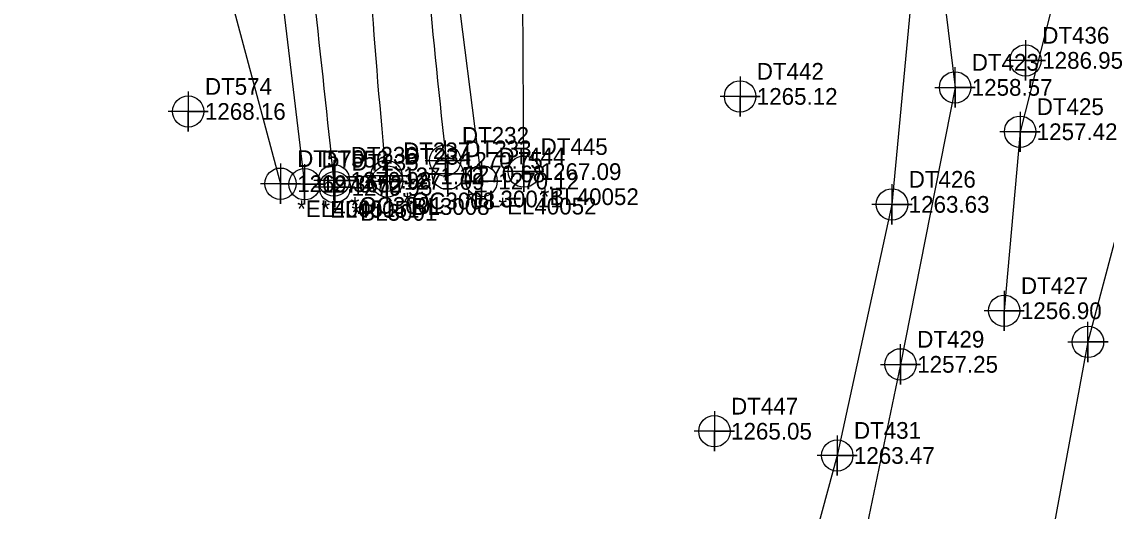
# Model space of a CAD drawing. Extents: x 1391270 to 1392151, y 960049 to 960667.
# Drawn here: x 1391450.5 to 1391612.7, y 960262.4 to 960335.6 of the extents above; entities that cross this region are included whole.
import ezdxf

# ---------------------------------------------------------------- set-up
doc = ezdxf.new("R2010")
doc.units = 0
for name, color, linetype in [('Cogo Default Point CELL', 7, 'Continuous'), ('COGO Default Point Elevation', 7, 'Continuous'), ('COGO Default Point Number', 7, 'Continuous'), ('Exist DTM Breakline', 7, 'Continuous'), ('Exist DTM Breakline Cogo Comment', 7, 'Continuous'), ('Exist DTM Breakline Cogo Elevation', 7, 'Continuous'), ('Exist DTM Breakline Cogo Number', 7, 'Continuous'), ('Exist DTM Breakline Cogo Point CELL', 7, 'Continuous'), ('Exist DTM Breakline Underwater', 7, 'Continuous'), ('Exist DTM Breakline Underwater Cogo Elevation', 7, 'Continuous'), ('Exist DTM Breakline Underwater Cogo Number', 7, 'Continuous'), ('Exist DTM Breakline Underwater Cogo Point CELL', 7, 'Continuous'), ('Exist DTM Crownline', 7, 'Continuous'), ('Exist DTM Crownline Cogo Comment', 7, 'Continuous'), ('Exist DTM Crownline Cogo Elevation', 7, 'Continuous'), ('Exist DTM Crownline Cogo Number', 7, 'Continuous'), ('Exist DTM Crownline Cogo Point CELL', 7, 'Continuous'), ('Exist DTM Regular Point CELL', 7, 'Continuous'), ('Exist DTM Regular Point Cogo Elevation', 7, 'Continuous'), ('Exist DTM Regular Point Cogo Number', 7, 'Continuous'), ('Exist Hydro Stream or Body of Water', 7, 'Continuous'), ('Exist Hydro Stream or Body of Water Cogo Elevation', 7, 'Continuous'), ('Exist Hydro Stream or Body of Water Cogo Number', 7, 'Continuous'), ('Exist Hydro Stream or Body of Water Cogo Point CELL', 7, 'Continuous'), ('Exist Roads EOP', 7, 'Continuous'), ('Exist Roads EOP Cogo Comment', 7, 'Continuous'), ('Exist Roads EOP Cogo Elevation', 7, 'Continuous'), ('Exist Roads EOP Cogo Number', 7, 'Continuous'), ('Exist Roads EOP Cogo Point CELL', 7, 'Continuous'), ('Exist Utilities Power UG Cable Cogo Elevation', 7, 'Continuous'), ('Exist Utilities Power UG Cable Cogo Number', 7, 'Continuous'), ('Exist Utilities Power UG Cable Cogo Point CELL', 7, 'Continuous')]:
    doc.layers.add(name, color=color, linetype=linetype)

msp = doc.modelspace()

# ---------------------------------------------------------------- linework, layer by layer
at = {"layer": 'Cogo Default Point CELL'}
for points in [[(1391513.803, 960317.83), (1391513.803, 960314.83)], [(1391510.803, 960314.83), (1391513.803, 960314.83)], [(1391513.803, 960314.83), (1391516.803, 960314.83)], [(1391513.803, 960314.83), (1391513.803, 960311.83)]]:
    msp.add_lwpolyline(points, dxfattribs=at)
msp.add_circle((1391513.803, 960314.83), 2.344, dxfattribs=at)
at = {"layer": 'Exist DTM Breakline'}
msp.add_line((1391525.576, 960313.163), (1391525.367, 960351.939), dxfattribs=at)
for points in [[(1391316.128, 960578.463), (1391335.373, 960567.825), (1391355.688, 960547.259), (1391385.482, 960507.01), (1391423.359, 960476.875), (1391439.432, 960458.285), (1391460.969, 960427.473), (1391472.339, 960397.865), (1391475.509, 960385.212), (1391483.88, 960383.187), (1391486.523, 960363.38), (1391492.773, 960311.276)], [(1391593.208, 960393.183), (1391584.528, 960353.643), (1391570.827, 960358.056), (1391556.983, 960362.658), (1391528.086, 960376.935), (1391520.577, 960378.658), (1391515.927, 960368.512), (1391514.98, 960345.087), (1391519.249, 960311.75)], [(1391421.76, 960362.297), (1391457.674, 960355.681), (1391474.205, 960361.463), (1391477.78, 960353.817), (1391489.16, 960311.358)], [(1391519.093, 960354.373), (1391532.168, 960353.935), (1391567.843, 960342.958), (1391583.917, 960343.284), (1391580.633, 960308.263), (1391572.441, 960270.705), (1391562.786, 960235.192)]]:
    msp.add_lwpolyline(points, dxfattribs=at)
at = {"layer": 'Exist DTM Breakline Cogo Point CELL'}
for points in [[(1391525.576, 960316.163), (1391525.576, 960310.163), (1391525.576, 960313.163), (1391528.576, 960313.163), (1391522.576, 960313.163)], [(1391489.16, 960314.358), (1391489.16, 960308.358), (1391489.16, 960311.358), (1391492.16, 960311.358), (1391486.16, 960311.358)], [(1391492.773, 960314.276), (1391492.773, 960308.276), (1391492.773, 960311.276), (1391495.773, 960311.276), (1391489.773, 960311.276)], [(1391519.249, 960314.75), (1391519.249, 960308.75), (1391519.249, 960311.75), (1391522.249, 960311.75), (1391516.249, 960311.75)], [(1391580.633, 960311.263), (1391580.633, 960305.263), (1391580.633, 960308.263), (1391583.633, 960308.263), (1391577.633, 960308.263)], [(1391572.441, 960273.705), (1391572.441, 960267.705), (1391572.441, 960270.705), (1391575.441, 960270.705), (1391569.441, 960270.705)]]:
    msp.add_lwpolyline(points, dxfattribs=at)
for centre in [(1391525.576, 960313.163), (1391489.16, 960311.358), (1391492.773, 960311.276), (1391519.249, 960311.75), (1391580.633, 960308.263), (1391572.441, 960270.705)]:
    msp.add_circle(centre, 2.344, dxfattribs=at)
at = {"layer": 'Exist DTM Breakline Underwater'}
msp.add_lwpolyline([(1391637.721, 960501.208), (1391621.569, 960466.64), (1391617.066, 960434.832), (1391615.14, 960379.594), (1391599.785, 960319.127), (1391597.418, 960292.355)], dxfattribs=at)
at = {"layer": 'Exist DTM Breakline Underwater Cogo Point CELL'}
for points in [[(1391599.785, 960322.127), (1391599.785, 960316.127), (1391599.785, 960319.127), (1391602.785, 960319.127), (1391596.785, 960319.127)], [(1391597.418, 960295.355), (1391597.418, 960289.355), (1391597.418, 960292.355), (1391600.418, 960292.355), (1391594.418, 960292.355)]]:
    msp.add_lwpolyline(points, dxfattribs=at)
for centre in [(1391599.785, 960319.127), (1391597.418, 960292.355)]:
    msp.add_circle(centre, 2.344, dxfattribs=at)
at = {"layer": 'Exist DTM Crownline'}
msp.add_line((1391505.11, 960311.696), (1391505.005, 960312.528), dxfattribs=at)
msp.add_spline([(1391505.005, 960312.528), (1391502.717, 960340.608), (1391501.701, 960372.252), (1391502.238, 960403.877), (1391504.663, 960427.16)], degree=3, dxfattribs=at)
at = {"layer": 'Exist DTM Crownline Cogo Point CELL'}
for points in [[(1391505.005, 960315.528), (1391505.005, 960309.528), (1391505.005, 960312.528), (1391508.005, 960312.528), (1391502.005, 960312.528)], [(1391505.11, 960314.696), (1391505.11, 960308.696), (1391505.11, 960311.696), (1391508.11, 960311.696), (1391502.11, 960311.696)]]:
    msp.add_lwpolyline(points, dxfattribs=at)
for centre in [(1391505.005, 960312.528), (1391505.11, 960311.696)]:
    msp.add_circle(centre, 2.344, dxfattribs=at)
at = {"layer": 'Exist DTM Regular Point CELL'}
for points in [[(1391557.909, 960327.412), (1391557.909, 960321.412), (1391557.909, 960324.412), (1391560.909, 960324.412), (1391554.909, 960324.412)], [(1391475.36, 960325.161), (1391475.36, 960319.161), (1391475.36, 960322.161), (1391478.36, 960322.161), (1391472.36, 960322.161)], [(1391554.064, 960277.332), (1391554.064, 960271.332), (1391554.064, 960274.332), (1391557.064, 960274.332), (1391551.064, 960274.332)]]:
    msp.add_lwpolyline(points, dxfattribs=at)
for centre in [(1391557.909, 960324.412), (1391475.36, 960322.161), (1391554.064, 960274.332)]:
    msp.add_circle(centre, 2.344, dxfattribs=at)
at = {"layer": 'Exist Hydro Stream or Body of Water'}
for points in [[(1391649.062, 960494.038), (1391648.634, 960466.546), (1391627.196, 960433.7), (1391623.135, 960411.167), (1391625.85, 960360.364), (1391618.453, 960319.772), (1391609.949, 960287.686), (1391599.63, 960231.778)], [(1391525.646, 960360.725), (1391533.691, 960355.656), (1391551.222, 960351.349), (1391566.005, 960349.028), (1391587.602, 960346.087), (1391590.063, 960325.761), (1391581.908, 960284.337), (1391574.185, 960247.222), (1391569.673, 960235.504)]]:
    msp.add_lwpolyline(points, dxfattribs=at)
at = {"layer": 'Exist Hydro Stream or Body of Water Cogo Point CELL'}
for points in [[(1391587.063, 960325.761), (1391593.063, 960325.761), (1391590.063, 960325.761), (1391590.063, 960322.761), (1391590.063, 960328.761)], [(1391606.949, 960287.686), (1391612.949, 960287.686), (1391609.949, 960287.686), (1391609.949, 960284.686), (1391609.949, 960290.686)], [(1391578.908, 960284.337), (1391584.908, 960284.337), (1391581.908, 960284.337), (1391581.908, 960281.337), (1391581.908, 960287.337)]]:
    msp.add_lwpolyline(points, dxfattribs=at)
for centre in [(1391590.063, 960325.761), (1391609.949, 960287.686), (1391581.908, 960284.337)]:
    msp.add_circle(centre, 2.344, dxfattribs=at)
at = {"layer": 'Exist Roads EOP'}
msp.add_line((1391497.292, 960310.818), (1391497.16, 960311.857), dxfattribs=at)
for points in [[(1391497.16, 960311.857), (1391494.199, 960339.333), (1391490.437, 960370.67), (1391484.795, 960409.189), (1391479.352, 960429.561), (1391471.345, 960448.702), (1391460.843, 960466.873), (1391449.093, 960483.056), (1391440.139, 960491.898), (1391403.899, 960524.912), (1391366.94, 960558.603)], [(1391553.715, 960387.967), (1391548.413, 960392.843), (1391543.408, 960395.581), (1391535.709, 960395.746), (1391529.074, 960394.424), (1391522.155, 960390.501), (1391514.618, 960381.223), (1391511.262, 960369.19), (1391511.324, 960340.675), (1391514.177, 960312.818)]]:
    msp.add_spline(points, degree=3, dxfattribs=at)
at = {"layer": 'Exist Roads EOP Cogo Point CELL'}
for points in [[(1391514.177, 960315.818), (1391514.177, 960309.818), (1391514.177, 960312.818), (1391517.177, 960312.818), (1391511.177, 960312.818)], [(1391497.16, 960314.857), (1391497.16, 960308.857), (1391497.16, 960311.857), (1391500.16, 960311.857), (1391494.16, 960311.857)], [(1391497.292, 960313.818), (1391497.292, 960307.818), (1391497.292, 960310.818), (1391500.292, 960310.818), (1391494.292, 960310.818)]]:
    msp.add_lwpolyline(points, dxfattribs=at)
for centre in [(1391514.177, 960312.818), (1391497.16, 960311.857), (1391497.292, 960310.818)]:
    msp.add_circle(centre, 2.344, dxfattribs=at)
at = {"layer": 'Exist Utilities Power UG Cable Cogo Point CELL'}
msp.add_lwpolyline([(1391600.609, 960332.803), (1391600.609, 960326.803), (1391600.609, 960329.803), (1391603.609, 960329.803), (1391597.609, 960329.803)], dxfattribs=at)
msp.add_circle((1391600.609, 960329.803), 2.344, dxfattribs=at)

# ---------------------------------------------------------------- texts
at = {"layer": 'COGO Default Point Elevation'}
msp.add_text('1270.75', height=2.5, dxfattribs=at).set_placement((1391516.303, 960313.58))
at = {"layer": 'COGO Default Point Number'}
msp.add_text('DT232', height=2.5, dxfattribs=at).set_placement((1391516.303, 960317.33))
at = {"layer": 'Exist DTM Breakline Cogo Comment'}
for s, p in [('*BL40052', (1391528.076, 960308.163)), ('*EL40051', (1391491.66, 960306.358)), ('*EL40051', (1391495.273, 960306.276)), ('*EL40052', (1391521.749, 960306.75))]:
    msp.add_text(s, height=2.5, dxfattribs=at).set_placement(p)
at = {"layer": 'Exist DTM Breakline Cogo Elevation'}
for s, p in [('1267.09', (1391528.076, 960311.913)), ('1269.36', (1391491.66, 960310.108)), ('1270.52', (1391495.273, 960310.026)), ('1270.12', (1391521.749, 960310.5)), ('1263.63', (1391583.133, 960307.013)), ('1263.47', (1391574.941, 960269.455))]:
    msp.add_text(s, height=2.5, dxfattribs=at).set_placement(p)
at = {"layer": 'Exist DTM Breakline Cogo Number'}
for s, p in [('DT445', (1391528.076, 960315.663)), ('DT570', (1391491.66, 960313.858)), ('DT556', (1391495.273, 960313.776)), ('DT444', (1391521.749, 960314.25)), ('DT426', (1391583.133, 960310.763)), ('DT431', (1391574.941, 960273.205))]:
    msp.add_text(s, height=2.5, dxfattribs=at).set_placement(p)
at = {"layer": 'Exist DTM Breakline Underwater Cogo Elevation'}
for s, p in [('1257.42', (1391602.285, 960317.877)), ('1256.90', (1391599.918, 960291.105))]:
    msp.add_text(s, height=2.5, dxfattribs=at).set_placement(p)
at = {"layer": 'Exist DTM Breakline Underwater Cogo Number'}
for s, p in [('DT425', (1391602.285, 960321.627)), ('DT427', (1391599.918, 960294.855))]:
    msp.add_text(s, height=2.5, dxfattribs=at).set_placement(p)
at = {"layer": 'Exist DTM Crownline Cogo Comment'}
for s, p in [('*OC3008', (1391507.505, 960307.528)), ('*BL3008', (1391507.61, 960306.696))]:
    msp.add_text(s, height=2.5, dxfattribs=at).set_placement(p)
at = {"layer": 'Exist DTM Crownline Cogo Elevation'}
for s, p in [('1271.12', (1391507.505, 960311.278)), ('1271.09', (1391507.61, 960310.446))]:
    msp.add_text(s, height=2.5, dxfattribs=at).set_placement(p)
at = {"layer": 'Exist DTM Crownline Cogo Number'}
for s, p in [('DT237', (1391507.505, 960315.028)), ('DT234', (1391507.61, 960314.196))]:
    msp.add_text(s, height=2.5, dxfattribs=at).set_placement(p)
at = {"layer": 'Exist DTM Regular Point Cogo Elevation'}
for s, p in [('1265.12', (1391560.409, 960323.162)), ('1268.16', (1391477.86, 960320.911)), ('1265.05', (1391556.564, 960273.082))]:
    msp.add_text(s, height=2.5, dxfattribs=at).set_placement(p)
at = {"layer": 'Exist DTM Regular Point Cogo Number'}
for s, p in [('DT442', (1391560.409, 960326.912)), ('DT574', (1391477.86, 960324.661)), ('DT447', (1391556.564, 960276.832))]:
    msp.add_text(s, height=2.5, dxfattribs=at).set_placement(p)
at = {"layer": 'Exist Hydro Stream or Body of Water Cogo Elevation'}
for s, p in [('1258.57', (1391592.563, 960324.511)), ('1257.25', (1391584.408, 960283.087))]:
    msp.add_text(s, height=2.5, dxfattribs=at).set_placement(p)
at = {"layer": 'Exist Hydro Stream or Body of Water Cogo Number'}
for s, p in [('DT423', (1391592.563, 960328.261)), ('DT429', (1391584.408, 960286.837))]:
    msp.add_text(s, height=2.5, dxfattribs=at).set_placement(p)
at = {"layer": 'Exist Roads EOP Cogo Comment'}
for s, p in [('*EL30011', (1391516.677, 960307.818)), ('*OC3001', (1391499.66, 960306.857)), ('*BL3001', (1391499.792, 960305.818))]:
    msp.add_text(s, height=2.5, dxfattribs=at).set_placement(p)
at = {"layer": 'Exist Roads EOP Cogo Elevation'}
for s, p in [('1270.68', (1391516.677, 960311.568)), ('1270.98', (1391499.66, 960310.607)), ('1270.95', (1391499.792, 960309.568))]:
    msp.add_text(s, height=2.5, dxfattribs=at).set_placement(p)
at = {"layer": 'Exist Roads EOP Cogo Number'}
for s, p in [('DT236', (1391499.66, 960314.357)), ('DT233', (1391516.677, 960315.318)), ('DT235', (1391499.792, 960313.318))]:
    msp.add_text(s, height=2.5, dxfattribs=at).set_placement(p)
at = {"layer": 'Exist Utilities Power UG Cable Cogo Elevation'}
msp.add_text('1286.95', height=2.5, dxfattribs=at).set_placement((1391603.109, 960328.553))
at = {"layer": 'Exist Utilities Power UG Cable Cogo Number'}
msp.add_text('DT436', height=2.5, dxfattribs=at).set_placement((1391603.109, 960332.303))

doc.saveas('drawing.dxf')
